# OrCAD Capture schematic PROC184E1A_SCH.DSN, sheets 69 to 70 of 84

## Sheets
69 28. SoM PMIC A: size C; title: PMIC A; note: PROC184_SCH
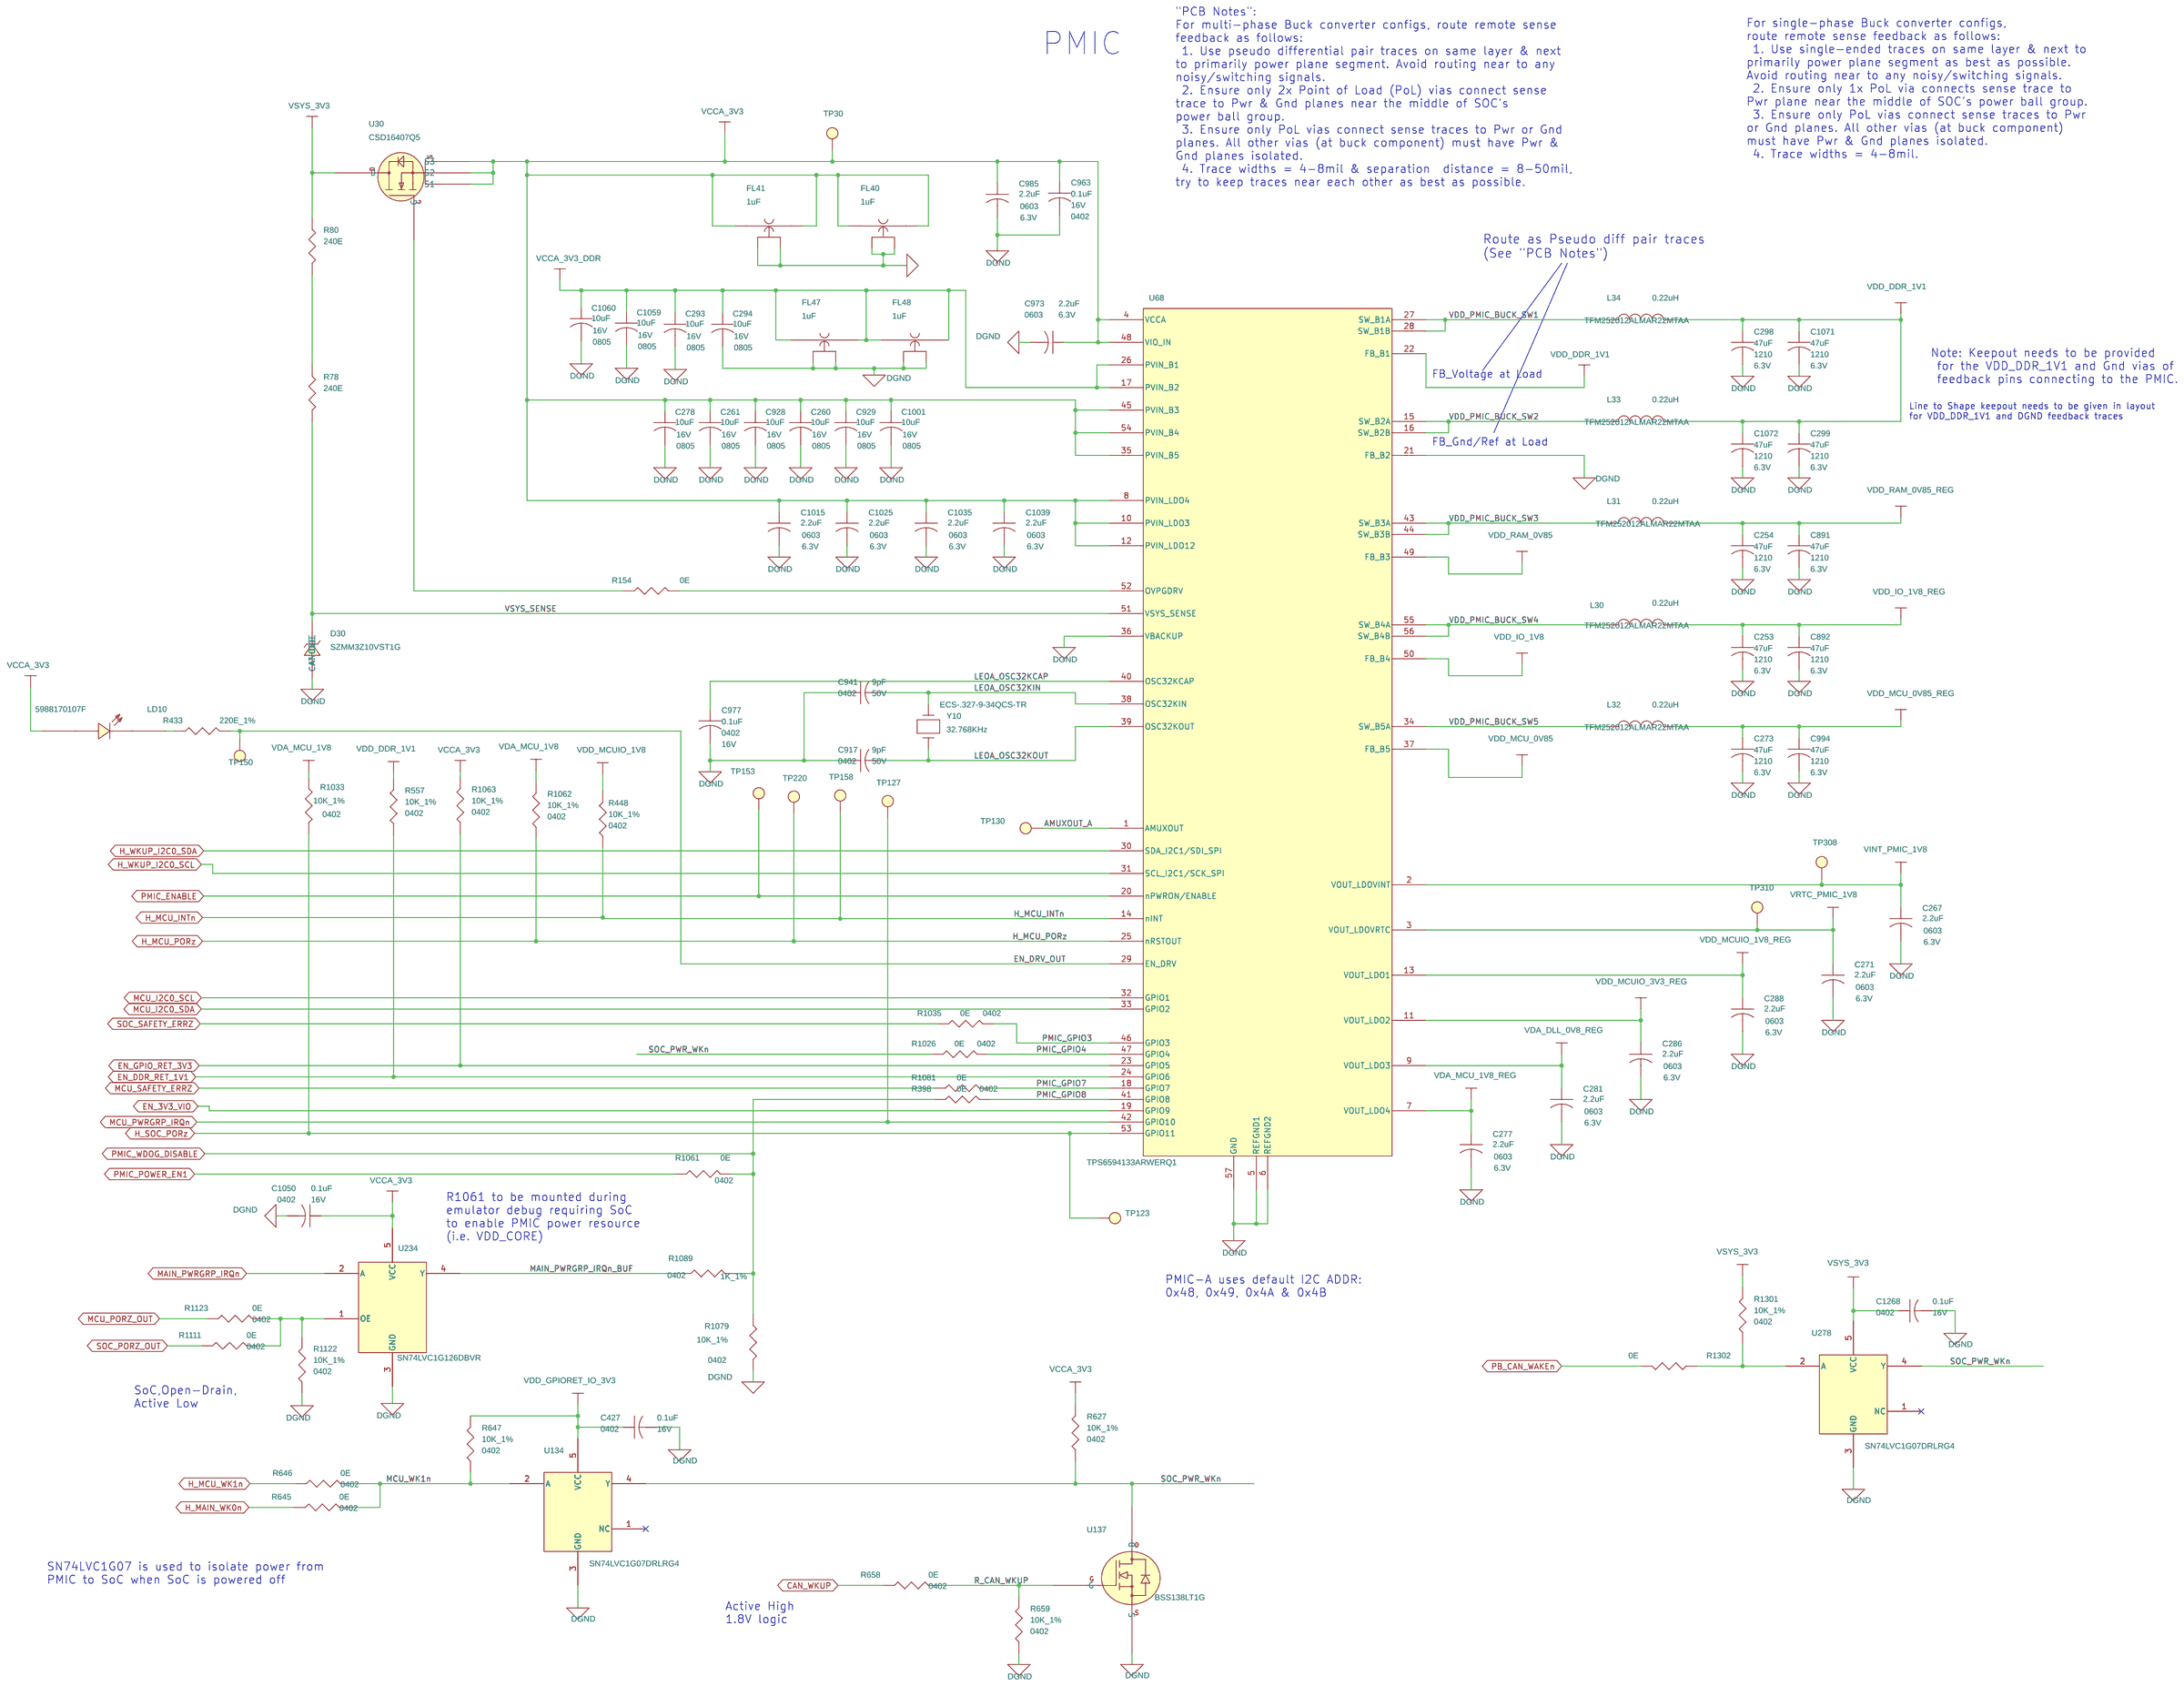
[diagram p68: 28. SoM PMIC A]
70 29. SOC CPU HCPS-A: size C; title: HCPS A; note: PROC184_SCH
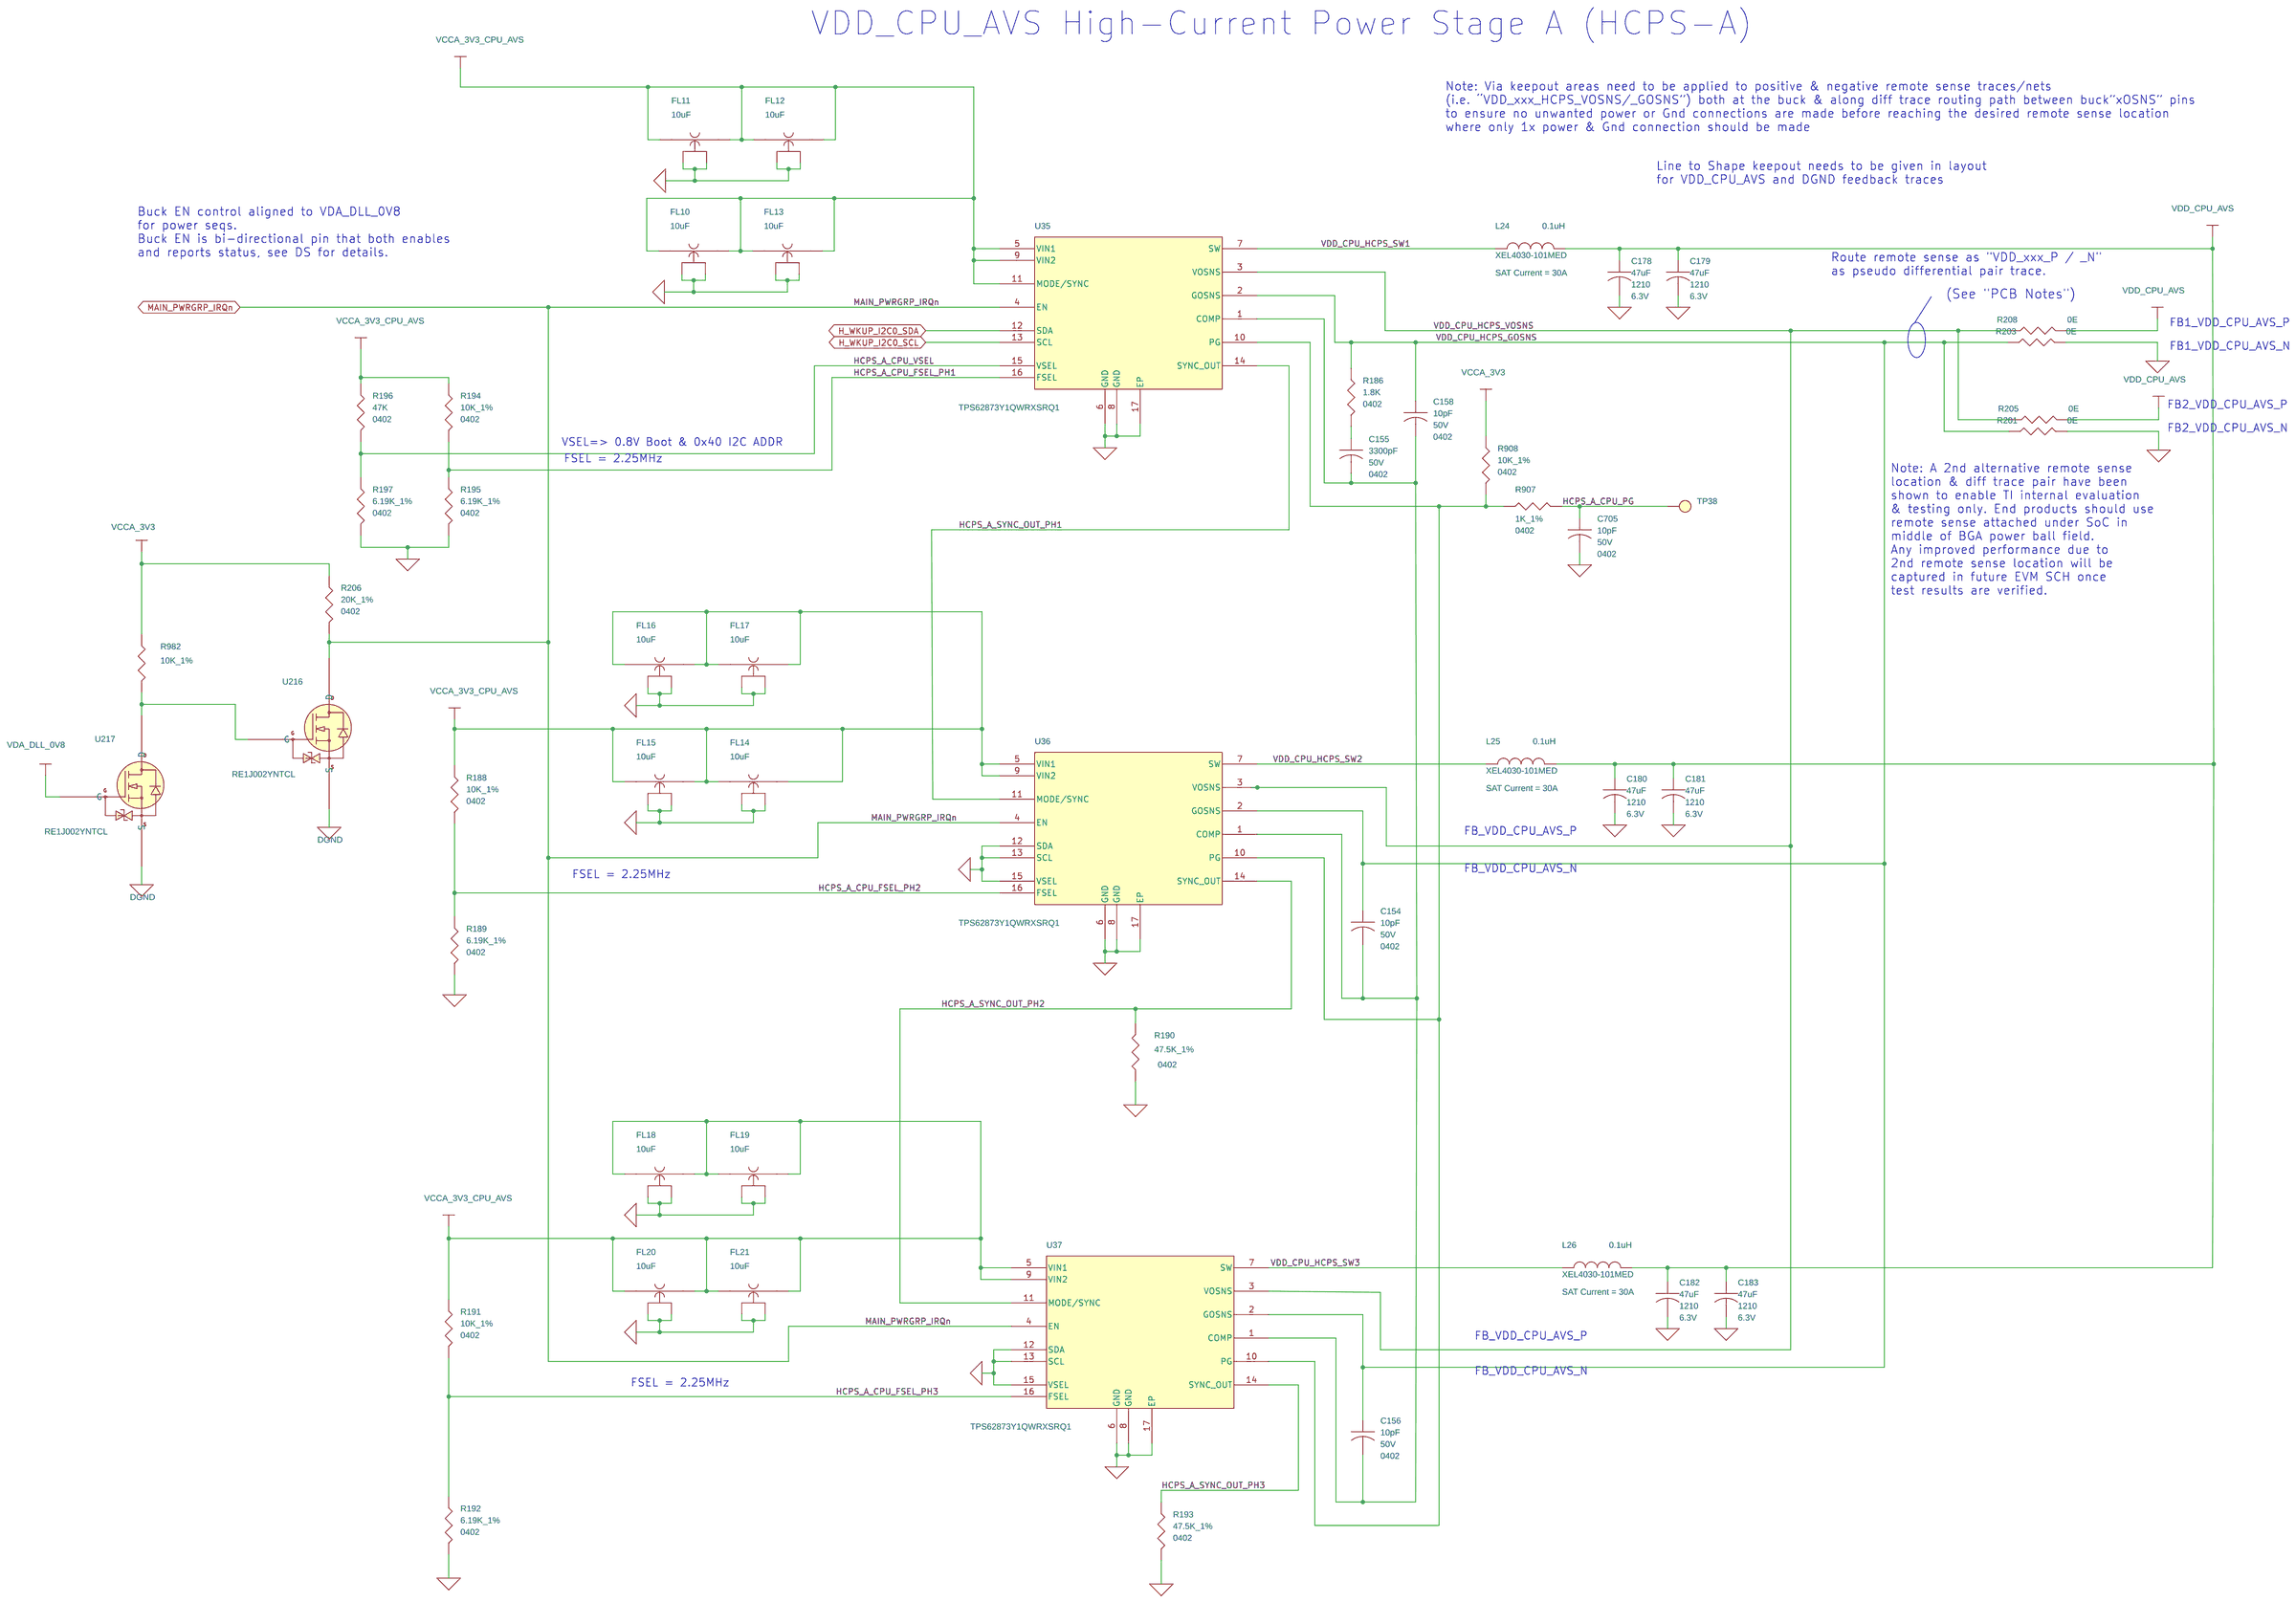
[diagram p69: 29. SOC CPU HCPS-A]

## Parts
sheet 28. SoM PMIC A
C253  47uF  [CAP1210_2-75]
C254  47uF  [CAP1210_2-75]
C260  10uF  [CAP0805_1-5]
C261  10uF  [CAP0805_1-5]
C267  2.2uF  [CAP0603_1]
C271  2.2uF  [CAP0603_1]
C273  47uF  [CAP1210_2-75]
C277  2.2uF  [CAP0603_1]
C278  10uF  [CAP0805_1-5]
C281  2.2uF  [CAP0603_1]
C286  2.2uF  [CAP0603_1]
C288  2.2uF  [CAP0603_1]
C293  10uF  [CAP0805_1-5]
C294  10uF  [CAP0805_1-5]
C298  47uF  [CAP1210_2-75]
C299  47uF  [CAP1210_2-75]
C427  0.1uF  [CAP0402_0-75]
C891  47uF  [CAP1210_2-75]
C892  47uF  [CAP1210_2-75]
C917  9pF  [CAP0402_0-75]
C928  10uF  [CAP0805_1-5]
C929  10uF  [CAP0805_1-5]
C941  9pF  [CAP0402_0-75]
C963  0.1uF  [CAP0402_0-75]
C973  2.2uF  [CAP0603_1]
C977  0.1uF  [CAP0402_0-75]
C985  2.2uF  [CAP0603_1]
C994  47uF  [CAP1210_2-75]
C1001  10uF  [CAP0805_1-5]
C1015  2.2uF  [CAP0603_1]
C1025  2.2uF  [CAP0603_1]
C1035  2.2uF  [CAP0603_1]
C1039  2.2uF  [CAP0603_1]
C1050  0.1uF  [CAP0402_0-75]
C1059  10uF  [CAP0805_1-5]
C1060  10uF  [CAP0805_1-5]
C1071  47uF  [CAP1210_2-75]
C1072  47uF  [CAP1210_2-75]
C1268  0.1uF  [CAP0402_0-75]
D30  SZMM3Z10VST1G  [DIO_SOD323_1-1]
FL40  1uF  [EMIFIL_NFM15CC_0402_0-5_TI]
FL41  1uF  [EMIFIL_NFM15CC_0402_0-5_TI]
FL47  1uF  [EMIFIL_NFM15CC_0402_0-5_TI]
FL48  1uF  [EMIFIL_NFM15CC_0402_0-5_TI]
L30  0.22uH  [IND1008_1-2]
L31  0.22uH  [IND1008_1-2]
L32  0.22uH  [IND1008_1-2]
L33  0.22uH  [IND1008_1-2]
L34  0.22uH  [IND1008_1-2]
LD10  5988170107F  [LED_0805_0-7]
R78  240E  [RES0402_0-5]
R80  240E  [RES0402_0-5]
R154  0E  [RES0402_0-5]
R398  0E  [RES0402_0-5]
R433  220E_1%  [RES0402_0-5]
R448  10K_1%  [RES0402_0-5]
R557  10K_1%  [RES0402_0-5]
R627  10K_1%  [RES0402_0-5]
R645  0E  [RES0402_0-5]
R646  0E  [RES0402_0-5]
R647  10K_1%  [RES0402_0-5]
R658  0E  [RES0402_0-5]
R659  10K_1%  [RES0402_0-5]
R1026  0E  [RES0402_0-5]
R1033  10K_1%  [RES0402_0-5]
R1035  0E  [RES0402_0-5]
R1061  0E  [RES0402_0-5]
R1062  10K_1%  [RES0402_0-5]
R1063  10K_1%  [RES0402_0-5]
R1079  10K_1%  [RES0402_0-5]
R1081  0E  [RES0402_0-5]
R1089  1K_1%  [RES0402_0-5]
R1111  0E  [RES0402_0-5]
R1122  10K_1%  [RES0402_0-5]
R1123  0E  [RES0402_0-5]
R1301  10K_1%  [RES0402_0-5]
R1302  0E  [RES0402_0-5]
TP30  TP30_SMD  [TP30_SMD]
TP123  TP30_SMD  [TP30_SMD]
TP127  TP30_SMD  [TP30_SMD]
TP130  TP30_SMD  [TP30_SMD]
TP150  TP30_SMD  [TP30_SMD]
TP153  TP30_SMD  [TP30_SMD]
TP158  TP30_SMD  [TP30_SMD]
TP220  TP30_SMD  [TP30_SMD]
TP308  TP30_SMD  [TP30_SMD]
TP310  TP30_SMD  [TP30_SMD]
U30  CSD16407Q5  [VSON8_CSD16407Q5_240X200_1-1]
U68  TPS6594133ARWERQ1  [VQFN56_19-68_320X320_0-9_EP6]
U134  SN74LVC1G07DRLRG4  [SOT553-5_0-6]
U137  BSS138LT1G  [SOT23-123_1-2]
U234  SN74LVC1G126DBVR  [SOT23-5_1-5]
U278  SN74LVC1G07DRLRG4  [SOT553-5_0-6]
Y10  32.768KHz  [XTAL_ECS-32_130X60_SMD_0-9]
sheet 29. SOC CPU HCPS-A
C154  10pF  [CAP0402_0-75]
C155  3300pF  [CAP0402_0-75]
C156  10pF  [CAP0402_0-75]
C158  10pF  [CAP0402_0-75]
C178  47uF  [CAP1210_2-75]
C179  47uF  [CAP1210_2-75]
C180  47uF  [CAP1210_2-75]
C181  47uF  [CAP1210_2-75]
C182  47uF  [CAP1210_2-75]
C183  47uF  [CAP1210_2-75]
C705  10pF  [CAP0402_0-75]
FL10  10uF  [EMIFIL_NFM18C_0603_0-7_TI]
FL11  10uF  [EMIFIL_NFM18C_0603_0-7_TI]
FL12  10uF  [EMIFIL_NFM18C_0603_0-7_TI]
FL13  10uF  [EMIFIL_NFM18C_0603_0-7_TI]
FL14  10uF  [EMIFIL_NFM18C_0603_0-7_TI]
FL15  10uF  [EMIFIL_NFM18C_0603_0-7_TI]
FL16  10uF  [EMIFIL_NFM18C_0603_0-7_TI]
FL17  10uF  [EMIFIL_NFM18C_0603_0-7_TI]
FL18  10uF  [EMIFIL_NFM18C_0603_0-7_TI]
FL19  10uF  [EMIFIL_NFM18C_0603_0-7_TI]
FL20  10uF  [EMIFIL_NFM18C_0603_0-7_TI]
FL21  10uF  [EMIFIL_NFM18C_0603_0-7_TI]
L24  0.1uH  [IND_XEL4030_170X170_SMD_3-2]
L25  0.1uH  [IND_XEL4030_170X170_SMD_3-2]
L26  0.1uH  [IND_XEL4030_170X170_SMD_3-2]
R186  1.8K  [RES0402_0-5]
R188  10K_1%  [RES0402_0-5]
R189  6.19K_1%  [RES0402_0-5]
R190  47.5K_1%  [RES0402_0-5]
R191  10K_1%  [RES0402_0-5]
R192  6.19K_1%  [RES0402_0-5]
R193  47.5K_1%  [RES0402_0-5]
R194  10K_1%  [RES0402_0-5]
R195  6.19K_1%  [RES0402_0-5]
R196  47K  [RES0402_0-5]
R197  6.19K_1%  [RES0402_0-5]
R201  0E  [RES0402_0-5]
R203  0E  [RES0402_0-5]
R205  0E  [RES0402_0-5]
R206  20K_1%  [RES0402_0-5]
R208  0E  [RES0402_0-5]
R907  1K_1%  [RES0402_0-5]
R908  10K_1%  [RES0402_0-5]
R982  10K_1%  [RES0402_0-5]
TP38  TP30_SMD  [TP30_SMD]
U35  TPS62873Y1QWRXSRQ1  [VQFN16_TPS62872-Q1_100X140_1-1]
U36  TPS62873Y1QWRXSRQ1  [VQFN16_TPS62872-Q1_100X140_1-1]
U37  TPS62873Y1QWRXSRQ1  [VQFN16_TPS62872-Q1_100X140_1-1]
U216  RE1J002YNTCL  [SOT416F-6_0-9]
U217  RE1J002YNTCL  [SOT416F-6_0-9]

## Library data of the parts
C178-C183 C253 C254 C273 C298 C299 C891 C892 C994 C1071 C1072 = CAP: CAP CERAMIC 47uF 6.3V 10% X7R AUTO 1210; Automotive Alternate_mfr_name: TDK; Automotive Alternate_mfr_part_number: CGA6P1X7S1A476M; Chkd/date: MANIRAJA/280918; Crtd /date: ALVY/280918; Custom_Duty: 15%; Customs_HS_Code: 85322990; Direct Alternate_mfr_name: TDK; Direct Alternate_mfr_part_number: CGA6P1X7S1A476M; Distributor_name: DIGIKEY; Distributor_part_number: 490-4844-1-ND; Footprint Path: Y:\MIS_DATABASE\Library\ALTIUM_TOOL\PCB_FOOTPRINTS\Altium_Footprint_Lib.PcbLib; Height: 2.70MM; Library Path: Y:\MIS_DATABASE\Library\ALTIUM_TOOL\SCHEMATICS_PARTS\MS_DISCRETE_Library.schlib; Manufacturer: MURATA; Mfr_name: MURATA; Mfr_part_number: GCM32ER70J476KE19L; Mistral Part No: 120018090056-R; Package: 1210; Part_type: CAPACITORS\CERAMIC; Project: TI_J7_SVB-DUT; RoHS: RoHS; Temperature: -55°C+125°C; Tolerance: 10%; Voltage: 6.3V; Wattage: NA; Weight: 110mg; Datasheet: Y:\MIS_DATABASE\DATASHEETS\CAPACITORS\MURATA-GCM-SER.PDF
C260 C261 C278 C293 C294 C928 C929 C1001 C1059 C1060 = CAP: CAP CERAMIC 10uF 16V 10% X5R 0805; Automotive Alternate_mfr_name: MURATA; Automotive Alternate_mfr_part_number: GCM21BR71A106KE22L; Chkd/date: SHREESHAIL/220506; Crtd /date: MAZHAR/150506; Custom_Duty: 15%; Customs_HS_Code: 85322990; Direct Alternate_mfr_name: SAMSUNG; Direct Alternate_mfr_part_number: CL21B106KPQNNNE; Distributor_name: DIGIKEY; Distributor_part_number: 490-3886-1-ND; Footprint Path: Y:\MIS_DATABASE\Library\ALTIUM_TOOL\PCB_FOOTPRINTS\Altium_Footprint_Lib.PcbLib; Height: 1.35MM; Library Path: Y:\MIS_DATABASE\Library\ALTIUM_TOOL\SCHEMATICS_PARTS\MS_DISCRETE_Library.schlib; Manufacturer: MURATA; Mfr_name: MURATA; Mfr_part_number: GRM21BR61C106KE15L; Mistral Part No: 120009030205-R; Package: 0805; Part_type: CAPACITORS\CERAMIC; Project: VOCERA; RoHS: RoHS; Temperature: -55°C+85°C; Tolerance: 10%; Voltage: 16V; Wattage: NA; Weight: 9.5mg; Datasheet: Y:\MIS_DATABASE\DATASHEETS\CAPACITORS\MURATA-GXX-SER_NOV17.PDF
C267 C271 C277 C281 C286 C288 C973 C985 C1015 C1025 C1035 C1039 = CAP: CAP CERAMIC 2.2uF 6.3V 10% X7R AUTO 0603; Automotive Alternate_mfr_name: TDK; Automotive Alternate_mfr_part_number: CGA3E1X7R0J225K080AC; Chkd/date: MANIRAJA/050419; Crtd /date: ALVY/050419; Custom_Duty: 15%; Customs_HS_Code: 85322990; Direct Alternate_mfr_name: TDK; Direct Alternate_mfr_part_number: CGA3E1X7R0J225K080AC; Distributor_name: DIGIKEY; Distributor_part_number: 490-5316-1-ND; Footprint Path: Y:\MIS_DATABASE\Library\ALTIUM_TOOL\PCB_FOOTPRINTS\Altium_Footprint_Lib.PcbLib; Height: 0.90MM; Library Path: Y:\MIS_DATABASE\Library\ALTIUM_TOOL\SCHEMATICS_PARTS\MS_DISCRETE_Library.schlib; Manufacturer: MURATA; Mfr_name: MURATA; Mfr_part_number: GCM188R70J225KE22D; Mistral Part No: 120019040009-R; Package: 0603; Part_type: CAPACITORS\CERAMIC; Project: J7ES_SOM_DUAL-LEO_PMIC; RoHS: RoHS; Temperature: -55°C+125°C; Tolerance: 10%; Voltage: 6.3V; Wattage: NA; Weight: 6.3mg; Datasheet: Y:\MIS_DATABASE\DATASHEETS\CAPACITORS\GCM188R70J225KE22.PDF
C427 C963 C977 C1050 C1268 = CAP: CAP CERAMIC 0.1uF 16V 10% X7R AUTO 0402; Automotive Alternate_mfr_name: TDK; Automotive Alternate_mfr_part_number: CGA2B1X7R1C104K050BC; Chkd/date: NAVEED/021014; Crtd /date: VASANTHA/300514; Custom_Duty: 15%; Customs_HS_Code: 85322990; Direct Alternate_mfr_name: MURATA; Direct Alternate_mfr_part_number: GCM155R71C104JA55D; Distributor_name: DIGIKEY; Distributor_part_number: 490-4759-1-ND; Footprint Path: Y:\MIS_DATABASE\Library\ALTIUM_TOOL\PCB_FOOTPRINTS\Altium_Footprint_Lib.PcbLib; Height: 0.55MM; Library Path: Y:\MIS_DATABASE\Library\ALTIUM_TOOL\SCHEMATICS_PARTS\MS_DISCRETE_Library.schlib; Manufacturer: MURATA; Mfr_name: MURATA; Mfr_part_number: GCM155R71C104KA55D; Mistral Part No: 120016070006-R; Package: 0402; Part_type: CAPACITORS\CERAMIC; Project: DCMIST_FPGA_CARD; RoHS: RoHS; Temperature: -55°C+125°C; Tolerance: 10%; Voltage: 16V; Wattage: NA; Weight: 6mg; Datasheet: Y:\MIS_DATABASE\DATASHEETS\CAPACITORS\MURATA-GCM-SER.PDF
C917 C941 = CAP: CAP CERAMIC 9pF 50V 0.5pF% C0G(NP0) AUTO 0402; Automotive Alternate_mfr_name: TDK; Automotive Alternate_mfr_part_number: CGA2B2C0G1H090D050BA; Chkd/date: VASANTHA/090419; Crtd /date: ALVY/090419; Custom_Duty: 15%; Customs_HS_Code: 85322990; Direct Alternate_mfr_name: TDK; Direct Alternate_mfr_part_number: CGA2B2C0G1H090D050BA; Distributor_name: DIGIKEY; Distributor_part_number: 445-12155-1-ND; Footprint Path: Y:\MIS_DATABASE\Library\ALTIUM_TOOL\PCB_FOOTPRINTS\Altium_Footprint_Lib.PcbLib; Height: 0.55MM; Library Path: Y:\MIS_DATABASE\Library\ALTIUM_TOOL\SCHEMATICS_PARTS\MS_DISCRETE_Library.schlib; Manufacturer: TDK CORPORATION; Mfr_name: TDK CORPORATION; Mfr_part_number: CGA2B2NP01H090D050BA; Mistral Part No: 120019040066-R; Package: 0402; Part_type: CAPACITORS\CERAMIC; Project: J7ES_SOM_DUAL-LEO_PMIC; RoHS: RoHS; Temperature: -55°C+150°C; Tolerance: 0.5pF%; Voltage: 50V; Wattage: NA; Weight: 0.65mg; Datasheet: Y:\MIS_DATABASE\DATASHEETS\CAPACITORS\CGA2B2NP01H090D050BA.PDF
D30 = DIODE_ZENER: DIODE ZENER 10V 300mW SOD323; Chkd/date: MANIRAJA/170419; Crtd /date: MANIRAJA/170419; Custom_Duty: 15%; Customs_HS_Code: 85412900; Distributor_name: DIGIKEY; Distributor_part_number: SZMM3Z10VST1GOSCT-ND; Footprint Path: Y:\MIS_DATABASE\Library\ALTIUM_TOOL\PCB_FOOTPRINTS\Altium_Footprint_Lib.PcbLib; Height: 1.10MM; Library Path: Y:\MIS_DATABASE\Library\ALTIUM_TOOL\SCHEMATICS_PARTS\MS_DISCRETE_Library.schlib; Manufacturer: ON SEMICONDUCTOR; Mfr_name: ON SEMICONDUCTOR; Mistral Part No: 130019040011-R; Package: SOD323; Part_type: DIODE\ZENER; Project: J7ES_SOM_DUAL-LEO_PMIC; RoHS: RoHS; Temperature: -65°C+150°C; Tolerance: NA; Voltage: 10V; Wattage: NA; Weight: NA; Datasheet: Y:\MIS_DATABASE\DATASHEETS\DISCRETES\DIODES\SZMM3ZXXXST1G.PDF
FL40 FL41 FL47 FL48 = CAP_NFM_TI: PASSIVE FILTER EMI 1uF 4V AUTO 0402; Chkd/date: MANIRAJA/251018; Crtd /date: ALVY/251018; Custom_Duty: 15%; Customs_HS_Code: 85412900; Distributor_name: NA; Distributor_part_number: NA; Footprint Path: Y:\MIS_DATABASE\Library\ALTIUM_TOOL\PCB_FOOTPRINTS\Altium_Footprint_Lib.PcbLib; Height: 0.50MM; Library Path: Y:\MIS_DATABASE\Library\ALTIUM_TOOL\SCHEMATICS_PARTS\MS_FILTER_Library.schlib; Mfr_name: MURATA; Mfr_part_number: NFM15HC105D0G_TI; Mistral Part No: 130018100050; Package: 0402; Part_type: FILTER; Project: TI_J7ES_EVM_SOM; RoHS: NA; Temperature: NA; Tolerance: NA; Voltage: 4V; Wattage: NA; Weight: NA; Datasheet: Y:\MIS_DATABASE\DATASHEETS\DISCRETES\INDUCTORS\NFM15CC223C1A3.PDF
L30-L34 = INDUCTOR: IND POWER 0.22uH 6.7A 20% AUTO 1008; Chkd/date: MANIRAJA/010620; Crtd /date: ALVY/290520; Custom_Duty: 24%; Customs_HS_Code: 85437099; Distributor_name: DIGIKEY; Distributor_part_number: 445-181487-1-ND; Footprint Path: Y:\MIS_DATABASE\Library\ALTIUM_TOOL\PCB_FOOTPRINTS\Altium_Footprint_Lib.PcbLib; Height: 1.20MM; Library Path: Y:\MIS_DATABASE\Library\ALTIUM_TOOL\SCHEMATICS_PARTS\MS_DISCRETE_Library.schlib; Manufacturer: TDK CORPORATION; Mfr_name: TDK CORPORATION; Mfr_part_number: TFM252012ALMAR22MTAA; Mistral Part No: 130020060001-R; Package: 1008; Project: J7VCL_SOM_LEO_HERA PMIC BRD; RoHS: RoHS; Temperature: -55°C+150°C; Tolerance: 20%; Voltage: NA; Wattage: NA; Weight: 35mg; Datasheet: Y:\MIS_DATABASE\DATASHEETS\DISCRETES\INDUCTORS\TFM252012ALMA-SER.PDF
LD10 = LED_598-8170-107F: LED ALINGAP GREEN CLEAR 0805; Chkd/date: MANIRAJA/230817; Crtd /date: SARANYA/070514; Custom_Duty: 24%; Customs_HS_Code: 85437099; Distributor_name: DIGIKEY; Distributor_part_number: 350-2044-1-ND; Footprint Path: Y:\MIS_DATABASE\Library\ALTIUM_TOOL\PCB_FOOTPRINTS\Altium_Footprint_Lib.PcbLib; Height: 0.70MM; Manufacturer: DIALIGHT; Mfr_name: DIALIGHT; Mistral Part No: 130014050065-R; Package: 0805; Part_type: OPTO\LED; Project: AEGIS GP BETA2; RoHS: RoHS; Temperature: -30°C+85°C; Tolerance: NA; Voltage: NA; Wattage: NA; Weight: NA; Datasheet: Y:\MIS_DATABASE\DATASHEETS\DISCRETES\LEDS\598-SER.PDF
R78 R80 = RESISTOR: RES 240E 1/16W 5% 0402; Chkd/date: VASANTHA/060117; Crtd /date: GEETHA/070606; Custom_Duty: 15%; Customs_HS_Code: 85332119; Distributor_name: DIGIKEY; Distributor_part_number: 311-240JRCT-ND; Footprint Path: Y:\MIS_DATABASE\Library\ALTIUM_TOOL\PCB_FOOTPRINTS\Altium_Footprint_Lib.PcbLib; Height: 0.40MM; Library Path: Y:\MIS_DATABASE\Library\ALTIUM_TOOL\SCHEMATICS_PARTS\MS_DISCRETE_Library.schlib; Manufacturer: YAGEO AMERICA; Mfr_name: YAGEO AMERICA; Mfr_part_number: RC0402JR-07240RL; Mistral Part No: 110009030544-R; Package: 0402; Part_type: RESISTORS\FIXED; Project: VOCERA; RoHS: RoHS; Temperature: -55°C+155°C; Tolerance: 5%; Voltage: NA; Wattage: 1/16W; Weight: 0.65mg; Datasheet: Y:\MIS_DATABASE\DATASHEETS\RESISTORS\RCXXXXL-SER_MAR18.PDF
R154 R201 R203 R205 R208 R398 R645 R646 R658 R1026 R1035 R1061 R1081 R1111 R1123 R1302 = RESISTOR: RES 0E 1/10W JUMPER 0402; Chkd/date: VASANTHA/061216; Crtd /date: NAVEED/201014; Custom_Duty: 15%; Customs_HS_Code: 85332119; Distributor_name: DIGIKEY; Distributor_part_number: P0.0JCT-ND; Footprint Path: Y:\MIS_DATABASE\Library\ALTIUM_TOOL\PCB_FOOTPRINTS\Altium_Footprint_Lib.PcbLib; Height: 0.40MM; IBISSP_MODLES: VALUE REPEATING 2 TIME; Library Path: Y:\MIS_DATABASE\Library\ALTIUM_TOOL\SCHEMATICS_PARTS\MS_DISCRETE_Library.schlib; Manufacturer: PANASONIC-ECG; Mfr_name: PANASONIC-ECG; Mfr_part_number: ERJ-2GE0R00X; Mistral Part No: 110018030052-R; Package: 0402; Part_type: RESISTORS\FIXED; Project: AEGIS POM; RoHS: RoHS; Temperature: -55°C+155°C; Tolerance: NA; Voltage: NA; Wattage: 1/10W; Weight: 0.8mg; Datasheet: Y:\MIS_DATABASE\DATASHEETS\RESISTORS\PAN-ERJSER_NOV17.PDF
R433 = RESISTOR: RES 220E 1/16W 1% 0402; Chkd/date: MANIRAJA/130917; Crtd /date: MANIRAJA/130917; Custom_Duty: 15%; Customs_HS_Code: 85332119; Distributor_name: DIGIKEY; Distributor_part_number: 311-220LRCT-ND; Footprint Path: Y:\MIS_DATABASE\Library\ALTIUM_TOOL\PCB_FOOTPRINTS\Altium_Footprint_Lib.PcbLib; Height: 0.40MM; Library Path: Y:\MIS_DATABASE\Library\ALTIUM_TOOL\SCHEMATICS_PARTS\MS_DISCRETE_Library.schlib; Manufacturer: YAGEO AMERICA; Mfr_name: YAGEO AMERICA; Mfr_part_number: RC0402FR-07220RL; Mistral Part No: 110019040169-R; Package: 0402; Part_type: RESISTORS\FIXED; Project: TI_SVB_MAXWELL_DUT; RoHS: RoHS; Temperature: -55°C+155°C; Tolerance: 1%; Voltage: NA; Wattage: 1/16W; Weight: 0.65mg; Datasheet: Y:\MIS_DATABASE\DATASHEETS\RESISTORS\RCXXXXL-SER_MAR18.PDF
R188 R191 R194 R448 R557 R627 R647 R659 R908 R1033 R1062 R1063 R1079 R1122 R1301 = RESISTOR: RES 10K 1/16W 1% 0402; Chkd/date: VASANTHA/201216; Crtd /date: GEETHA/290506; Custom_Duty: 15%; Customs_HS_Code: 85332119; Distributor_name: DIGIKEY; Distributor_part_number: 311-10.0KLRTR-ND; Footprint Path: Y:\MIS_DATABASE\Library\ALTIUM_TOOL\PCB_FOOTPRINTS\Altium_Footprint_Lib.PcbLib; Height: 0.40MM; Library Path: Y:\MIS_DATABASE\Library\ALTIUM_TOOL\SCHEMATICS_PARTS\MS_DISCRETE_Library.schlib; Manufacturer: YAGEO AMERICA; Mfr_name: YAGEO AMERICA; Mfr_part_number: RC0402FR-0710KL; Mistral Part No: 110015090015-R; Package: 0402; Part_type: RESISTORS\FIXED; Project: VOCERA; RoHS: RoHS; Temperature: -55°C+155°C; Tolerance: 1%; Voltage: NA; Wattage: 1/16W; Weight: 0.65mg; Datasheet: Y:\MIS_DATABASE\DATASHEETS\RESISTORS\RCXXXXL-SER_MAR18.PDF
R907 R1089 = RESISTOR: RES 1K 1/10W 1% 0402; Chkd/date: VASANTHA/281216; Crtd /date: MAZHAR/150506; Custom_Duty: 15%; Customs_HS_Code: 85332119; Distributor_name: DIGIKEY; Distributor_part_number: P1.00KLCT-ND; Footprint Path: Y:\MIS_DATABASE\Library\ALTIUM_TOOL\PCB_FOOTPRINTS\Altium_Footprint_Lib.PcbLib; Height: 0.40MM; Library Path: Y:\MIS_DATABASE\Library\ALTIUM_TOOL\SCHEMATICS_PARTS\MS_DISCRETE_Library.schlib; Manufacturer: PANASONIC-ECG; Mfr_name: PANASONIC-ECG; Mfr_part_number: ERJ-2RKF1001X; Mistral Part No: 110009030411-R; Package: 0402; Part_type: RESISTORS\FIXED; Project: VOCERA; RoHS: RoHS; Temperature: -55°C+155°C; Tolerance: 1%; Voltage: NA; Wattage: 1/10W; Weight: 0.8mg; Datasheet: Y:\MIS_DATABASE\DATASHEETS\RESISTORS\PAN-ERJSER_NOV17.PDF
TP30 TP38 TP123 TP127 TP130 TP150 TP153 TP158 TP220 TP308 TP310 = TESTPOINT: TESTPOINT CIR 30 SMD; Chkd/date: SHREESHAIL/171006; Crtd /date: MAZHAR/171006; Custom_Duty: NA; Customs_HS_Code: NA; Distributor_name: NA; Distributor_part_number: NA; Footprint Path: Y:\MIS_DATABASE\Library\ALTIUM_TOOL\PCB_FOOTPRINTS\Altium_Footprint_Lib.PcbLib; Height: NA; Library Path: Y:\MIS_DATABASE\Library\ALTIUM_TOOL\SCHEMATICS_PARTS\MS_DISCRETE_Library.schlib; MECHANICAL 3D STEP FILE: NA; Manufacturer: LOCAL; Mfr_name: LOCAL; Mistral Part No: 130009030930; Package: SMD; Project: BT MODULE_CSRBC04; RoHS: NA; Temperature: NA; Tolerance: NA; Voltage: NA; Wattage: NA; Weight: NA; Datasheet: NA
U30 = MOSFET_CSD17301Q5A: IC 25V N-CHANNEL NEXFET POWER MOSFET VSON-CLIP8; Chkd/date: ALVY/090322; Crtd /date: ALVY/090322; Custom_Duty: 15%; Customs_HS_Code: 85423100; Distributor_name: DIGIKEY; Distributor_part_number: 296-24252-1-ND; Footprint Path: Y:\MIS_DATABASE\Library\ALTIUM_TOOL\PCB_FOOTPRINTS\Altium_Footprint_Lib.PcbLib; Height: 1.05MM; Library Path: Y:\MIS_DATABASE\Library\ALTIUM_TOOL\SCHEMATICS_PARTS\MS_MOSFET_Library.schlib; Mfr_name: TEXAS INSTRUMENTS; Mistral Part No: 142022030005-R; Package: VSON-CLIP8; Part_type: ICS\POWER\MOSFET; Project: TI_J7AHP_EVM_BRD; RoHS: RoHS; Temperature: -55°C+150°C; Tolerance: NA; Voltage: 25V; Wattage: NA; Weight: 117.4mg; Datasheet: Y:\MIS_DATABASE\DATASHEETS\ICS\POWER\CSD16407Q5.PDF
U68 = TPS65941-Q1_VQFN56: IC POWER MANAGEMENT WITH 4-PHASE 14A BUCK VQFN56; Chkd/date: ALVY/280322; Crtd /date: ALVY/280322; Custom_Duty: 15%; Customs_HS_Code: 85423100; Distributor_name: NA; Distributor_part_number: NA; Footprint Path: Y:\MIS_DATABASE\Library\ALTIUM_TOOL\PCB_FOOTPRINTS\Altium_Footprint_Lib.PcbLib; Height: 0.90MM; Library Path: Y:\MIS_DATABASE\Library\ALTIUM_TOOL\SCHEMATICS_PARTS\MS_MISCPOWER_Library.schlib; Manufacturer: TEXAS INSTRUMENTS; Mfr_name: TEXAS INSTRUMENTS; Mistral Part No: 142022030021-R; Package: VQFN56; Part_type: ICS\POWER\MANAGEMENT; Project: TI_J7AHP_EVM_BRD; Remarks: CREATED SAME AS PTPS65941120RWERQ1; RoHS: RoHS; Temperature: -40°C+125°C; Tolerance: NA; Voltage: NA; Wattage: NA; Weight: NA; Datasheet: Y:\MIS_DATABASE\DATASHEETS\ICS\POWER\TPS65941-Q1.PDF
U134 U278 = SN74LVC1G07DRLRG4_SOT553-5: IC SINGLE BUFFER/DRIVER WITH OPEN-DRAIN OUTPUT SOT553-5; Chkd/date: RAGESH/111110; Crtd /date: MAZHAR/170907; Custom_Duty: 15%; Customs_HS_Code: 85423100; Distributor_name: DIGIKEY; Distributor_part_number: SN74LVC1G07DRLRG4-ND; Footprint Path: Y:\MIS_DATABASE\Library\ALTIUM_TOOL\PCB_FOOTPRINTS\Altium_Footprint_Lib.PcbLib; Height: 0.60MM; Library Path: Y:\MIS_DATABASE\Library\ALTIUM_TOOL\SCHEMATICS_PARTS\MS_LINEDRIVERRECEIVER_Library.schlib; Manufacturer: TEXAS INSTRUMENTS; Mfr_name: TEXAS INSTRUMENTS; Mistral Part No: 141009030406-R; Package: SOT553-5; Part_type: ICS\INTERFACE\LINE DRIVER; Project: SMART VIEW_IP CAMERA; RoHS: RoHS; Temperature: -40°C+125°C; Tolerance: NA; Voltage: NA; Wattage: NA; Weight: 2.8mg; Datasheet: Y:\MIS_DATABASE\DATASHEETS\ICS\INTERFACE\SN74LVC1G07-SER.PDF
U137 = MOSFET_BSS138W: IC MOSFET N-CHANNEL 50V 200mA SOT23-3; Chkd/date: MANIRAJA/250219; Crtd /date: JEBRAN/060416; Custom_Duty: 15%; Customs_HS_Code: 85423100; Distributor_name: DIGIKEY; Distributor_part_number: BSS138LT1GOSCT-ND; Footprint Path: Y:\MIS_DATABASE\Library\ALTIUM_TOOL\PCB_FOOTPRINTS\Altium_Footprint_Lib.PcbLib; Height: 1.11MM; Library Path: Y:\MIS_DATABASE\Library\ALTIUM_TOOL\SCHEMATICS_PARTS\MS_MOSFET_Library.schlib; Manufacturer: ON SEMICONDUCTOR; Mfr_name: ON SEMICONDUCTOR; Mistral Part No: 142016040001-R; Package: SOT23-3; Part_type: ICS\POWER\MOSFET; Project: LRDE_ABCM; RoHS: RoHS; Temperature: -55°C+150°C; Tolerance: NA; Voltage: NA; Wattage: NA; Weight: 8mg; Datasheet: Y:\MIS_DATABASE\DATASHEETS\DISCRETES\TRANSISTORS_FETS\BSS138LT1G.PDF
U234 = SN74LVC1G126DBVR_SOT23-5: IC SINGLE BUS BUFFER GATE WITH 3-STATE O/P SOT23-5; Chkd/date: MANIRAJA/130519; Crtd /date: MAZHAR/301106; Custom_Duty: 15%; Customs_HS_Code: 85423100; Distributor_name: DIGIKEY; Distributor_part_number: 296-11605-1-ND; Footprint Path: Y:\MIS_DATABASE\Library\ALTIUM_TOOL\PCB_FOOTPRINTS\Altium_Footprint_Lib.PcbLib; Height: 1.45MM; Library Path: Y:\MIS_DATABASE\Library\ALTIUM_TOOL\SCHEMATICS_PARTS\MS_GATE_Library.schlib; Mfr_name: TEXAS INSTRUMENTS; Mistral Part No: 141009030232-R; Package: SOT23-5; Part_type: ICS\DIGITAL\GATES; Project: PMP LCD BOARD; RoHS: RoHS; Temperature: -40°C+125°C; Tolerance: NA; Voltage: NA; Wattage: NA; Weight: 6.3mg; Datasheet: Y:\MIS_DATABASE\DATASHEETS\ICS\DIGITAL\GATES\SN74LVC1G126XXX.PDF
Y10 = CRY: CRY 32.768KHz 9pF SMD; Chkd/date: VASANTHA/090419; Crtd /date: ALVY/090419; Custom_Duty: 24%; Customs_HS_Code: 85439000; Distributor_name: DIGIKEY; Distributor_part_number: XC2160CT-ND; Footprint Path: Y:\MIS_DATABASE\Library\ALTIUM_TOOL\PCB_FOOTPRINTS\Altium_Footprint_Lib.PcbLib; Height: 0.90MM; Library Path: Y:\MIS_DATABASE\Library\ALTIUM_TOOL\SCHEMATICS_PARTS\MS_DISCRETE_Library.schlib; Manufacturer: ECS INC; Mfr_name: ECS INC; Mfr_part_number: ECS-.327-9-34QCS-TR; Mistral Part No: 130019040003-R; Package: SMD; Part_type: CRYSTAL; Project: J7ES_SOM_DUAL-LEO_PMIC; RoHS: RoHS; Temperature: -40°C+125°C; Tolerance: NA; Voltage: NA; Wattage: NA; Weight: 16mg; Datasheet: Y:\MIS_DATABASE\DATASHEETS\MISC\CRY_OSC\ECS-34Q.PDF
C154 C156 C158 C705 = CAP: CAP CERAMIC 10pF 50V 1% C0G(NP0) 0402; Automotive Alternate_mfr_name: TDK; Automotive Alternate_mfr_part_number: CGA2B1X7R1C104K050BC; Chkd/date: VASANTHA/200614; Crtd /date: NAVEED/170614; Custom_Duty: 15%; Customs_HS_Code: 85322990; Direct Alternate_mfr_name: MURATA; Direct Alternate_mfr_part_number: GCM155R71C104JA55D; Distributor_name: DIGIKEY; Distributor_part_number: 478-5717-1-ND; Footprint Path: Y:\MIS_DATABASE\Library\ALTIUM_TOOL\PCB_FOOTPRINTS\Altium_Footprint_Lib.PcbLib; Height: 0.55MM; Library Path: Y:\MIS_DATABASE\Library\ALTIUM_TOOL\SCHEMATICS_PARTS\MS_DISCRETE_Library.schlib; Manufacturer: AVX CORPORATION; Mfr_name: AVX CORPORATION; Mfr_part_number: 04025U100FAT2A; Mistral Part No: 120014060010-R; Package: 0402; Part_type: CAPACITORS\CERAMIC; Project: AEGIS_POM; RoHS: RoHS; Temperature: -55°C+125°C; Tolerance: 1%; Voltage: 50V; Wattage: NA; Weight: 0.65mg; Datasheet: Y:\MIS_DATABASE\DATASHEETS\CAPACITORS\AVX_MLC.PDF
C155 = CAP: CAP CERAMIC 3300pF 50V 10% X7R 0402; Automotive Alternate_mfr_name: TDK; Automotive Alternate_mfr_part_number: CGA2B1X7R1C104K050BC; Chkd/date: MANIRAJA/180817; Crtd /date: MANIRAJA/180817; Custom_Duty: 15%; Customs_HS_Code: 85322990; Direct Alternate_mfr_name: MURATA; Direct Alternate_mfr_part_number: GCM155R71C104JA55D; Distributor_name: DIGIKEY; Distributor_part_number: 490-3248-1-ND; Footprint Path: Y:\MIS_DATABASE\Library\ALTIUM_TOOL\PCB_FOOTPRINTS\Altium_Footprint_Lib.PcbLib; Height: 0.55MM; Library Path: Y:\MIS_DATABASE\Library\ALTIUM_TOOL\SCHEMATICS_PARTS\MS_DISCRETE_Library.schlib; Manufacturer: MURATA; Mfr_name: MURATA; Mfr_part_number: GRM155R71H332KA01D; Mistral Part No: 120009030367-R; Package: 0402; Part_type: CAPACITORS\CERAMIC; Project: DM8147_PCI CARD; RoHS: RoHS; Temperature: -55°C+125°C; Tolerance: 10%; Voltage: 50V; Wattage: NA; Weight: 6mg; Datasheet: Y:\MIS_DATABASE\DATASHEETS\CAPACITORS\MURATA-GXX-SER_NOV17.PDF
FL10-FL21 = CAP_NFM_TI: PASSIVE FILTER EMI 10uF 4V AUTO 0603; Chkd/date: MANIRAJA/251018; Crtd /date: ALVY/251018; Custom_Duty: 15%; Customs_HS_Code: 85412900; Distributor_name: NA; Distributor_part_number: NA; Footprint Path: Y:\MIS_DATABASE\Library\ALTIUM_TOOL\PCB_FOOTPRINTS\Altium_Footprint_Lib.PcbLib; Height: 0.70MM; Library Path: Y:\MIS_DATABASE\Library\ALTIUM_TOOL\SCHEMATICS_PARTS\MS_FILTER_Library.schlib; Mfr_name: MURATA; Mfr_part_number: NFM18HC106D0G_TI; Mistral Part No: 130018100049; Package: 0603; Part_type: FILTER; Project: TI_J7ES_EVM_SOM; RoHS: NA; Temperature: NA; Tolerance: NA; Voltage: 4V; Wattage: NA; Weight: NA; Datasheet: Y:\MIS_DATABASE\DATASHEETS\DISCRETES\INDUCTORS\NFM18HC-SER.PDF
L24-L26 = INDUCTOR: IND POWER 0.1uH 25.8A 20% SMD; Chkd/date: MANIRAJA/170122; Crtd /date: TAMILARASU/170122; Custom_Duty: 24%; Customs_HS_Code: 85437099; Distributor_name: MOUSER; Distributor_part_number: 994-XEL4030-101MED; Footprint Path: Y:\MIS_DATABASE\Library\ALTIUM_TOOL\PCB_FOOTPRINTS\Altium_Footprint_Lib.PcbLib; Height: 3.20MM; Library Path: Y:\MIS_DATABASE\Library\ALTIUM_TOOL\SCHEMATICS_PARTS\MS_DISCRETE_Library.schlib; Manufacturer: COILCRAFT; Mfr_name: COILCRAFT; Mfr_part_number: XEL4030-101MED; Mistral Part No: 130022010018-R; Package: SMD; Part #: 105324-1470R; Project: J7AHP_PROTO_BRD; RoHS: RoHS; SAT Current: 30A; Temperature: -40°C+125°C; Tolerance: 20%; Voltage: NA; Wattage: NA; Weight: 280mg; Datasheet: Y:\MIS_DATABASE\DATASHEETS\DISCRETES\INDUCTORS\XEL4030_JUN20.PDF
R186 = RESISTOR: RES 1.8K 1/16W 5% AUTO 0402; Chkd/date: MAZHAR/170709; Crtd /date: MAZHAR/200907; Custom_Duty: 15%; Customs_HS_Code: 85332119; Distributor_name: DIGIKEY; Distributor_part_number: RHM1.8KJCT-ND; Footprint Path: Y:\MIS_DATABASE\Library\ALTIUM_TOOL\PCB_FOOTPRINTS\Altium_Footprint_Lib.PcbLib; Height: 0.40MM; Library Path: Y:\MIS_DATABASE\Library\ALTIUM_TOOL\SCHEMATICS_PARTS\MS_DISCRETE_Library.schlib; Manufacturer: ROHM; Mfr_name: ROHM; Mfr_part_number: MCR01MZPJ182; Mistral Part No: 110009030147-R; Package: 0402; Part_type: RESISTORS\FIXED; Project: MARP; RoHS: RoHS; Temperature: -55°C+155°C; Tolerance: 5%; Voltage: NA; Wattage: 1/16W; Weight: 0.57mg; Datasheet: Y:\MIS_DATABASE\DATASHEETS\RESISTORS\MCR10.PDF
R189 R192 R195 R197 = RESISTOR: RES 6.19K 1/16W 1% 0402; Chkd/date: MANIRAJA/190122; Crtd /date: TAMILARASU/190122; Custom_Duty: 15%; Customs_HS_Code: 85332119; Distributor_name: DIGIKEY; Distributor_part_number: 311-6.19KLRCT-ND; Footprint Path: Y:\MIS_DATABASE\Library\ALTIUM_TOOL\PCB_FOOTPRINTS\Altium_Footprint_Lib.PcbLib; Height: 0.40MM; Library Path: Y:\MIS_DATABASE\Library\ALTIUM_TOOL\SCHEMATICS_PARTS\MS_DISCRETE_Library.schlib; Manufacturer: YAGEO AMERICA; Mfr_name: YAGEO AMERICA; Mfr_part_number: RC0402FR-076K19L; Mistral Part No: 110022010013-R; Package: 0402; Part_type: RESISTORS\FIXED; Project: J7AHP_PROTO_BRD; RoHS: RoHS; Temperature: -55°C+155°C; Tolerance: 1%; Voltage: NA; Wattage: 1/16W; Weight: 0.65mg; Datasheet: Y:\MIS_DATABASE\DATASHEETS\RESISTORS\RCXXXXL-SER_MAR18.PDF
R190 R193 = RESISTOR: RES 47.5K 1/16W 1% 0402; Chkd/date: MANIRAJA/170320; Crtd /date: MANIRAJA/170320; Custom_Duty: 15%; Customs_HS_Code: 85332119; Distributor_name: DIGIKEY; Distributor_part_number: 541-47.5KLCT-ND; Footprint Path: Y:\MIS_DATABASE\Library\ALTIUM_TOOL\PCB_FOOTPRINTS\Altium_Footprint_Lib.PcbLib; Height: 0.40MM; Library Path: Y:\MIS_DATABASE\Library\ALTIUM_TOOL\SCHEMATICS_PARTS\MS_DISCRETE_Library.schlib; Manufacturer: VISHAY; Mfr_name: VISHAY; Mfr_part_number: CRCW040247K5FKED; Mistral Part No: 110017010006-R; Package: 0402; Part_type: RESISTORS\FIXED; Project: TPR12_SVB; RoHS: RoHS; Temperature: -55°C+155°C; Tolerance: 1%; Voltage: NA; Wattage: 1/16W; Weight: 0.65mg; Datasheet: Y:\MIS_DATABASE\DATASHEETS\RESISTORS\CRCW0603.PDF
R196 = RESISTOR: RES 47K 1/10W 5% 0402; Chkd/date: VASANTHA/281216; Crtd /date: MAZHAR/120505; Custom_Duty: 15%; Customs_HS_Code: 85332119; Distributor_name: DIGIKEY; Distributor_part_number: P47KJCT-ND; Footprint Path: Y:\MIS_DATABASE\Library\ALTIUM_TOOL\PCB_FOOTPRINTS\Altium_Footprint_Lib.PcbLib; Height: 0.40MM; Library Path: Y:\MIS_DATABASE\Library\ALTIUM_TOOL\SCHEMATICS_PARTS\MS_DISCRETE_Library.schlib; Manufacturer: PANASONIC-ECG; Mfr_name: PANASONIC-ECG; Mfr_part_number: ERJ-2GEJ473X; Mistral Part No: 110009030882-R; Package: 0402; Part_type: RESISTORS\FIXED; Project: CTP02_REVA_BASE; RoHS: RoHS; Temperature: -55°C+155°C; Tolerance: 5%; Voltage: NA; Wattage: 1/10W; Weight: 0.8mg; Datasheet: Y:\MIS_DATABASE\DATASHEETS\RESISTORS\PAN-ERJSER_NOV17.PDF
R206 = RESISTOR: RES 20K 1/16W 1% 0402; Chkd/date: MAZHAR/280108; Crtd /date: USMAN/280108; Custom_Duty: 15%; Customs_HS_Code: 85332119; Distributor_name: DIGIKEY; Distributor_part_number: 311-20.0KLRCT-ND; Footprint Path: Y:\MIS_DATABASE\Library\ALTIUM_TOOL\PCB_FOOTPRINTS\Altium_Footprint_Lib.PcbLib; Height: 0.40MM; Library Path: Y:\MIS_DATABASE\Library\ALTIUM_TOOL\SCHEMATICS_PARTS\MS_DISCRETE_Library.schlib; Mfr_name: YAGEO AMERICA; Mfr_part_number: RC0402FR-0720KL; Mistral Part No: 110009030486-R; Package: 0402; Part_type: RESISTORS\FIXED; Project: TELEMETRY ENCODER; RoHS: RoHS; Temperature: -55°C+155°C; Tolerance: 1%; Voltage: NA; Wattage: 1/16W; Weight: 0.65mg; Datasheet: Y:\MIS_DATABASE\DATASHEETS\RESISTORS\RCXXXXL-SER_MAR18.PDF
R982 = RESISTOR: RES 10K 1/16W 1% 0402; Chkd/date: VASANTHA/201216; Crtd /date: GEETHA/290506; Custom_Duty: 15%; Customs_HS_Code: 85332119; Distributor_name: DIGIKEY; Distributor_part_number: 311-10.0KLRTR-ND; Footprint Path: Y:\MIS_DATABASE\Library\ALTIUM_TOOL\PCB_FOOTPRINTS\Altium_Footprint_Lib.PcbLib; Height: 0.40MM; Library Path: Y:\MIS_DATABASE\Library\ALTIUM_TOOL\SCHEMATICS_PARTS\MS_DISCRETE_Library.schlib; Mfr_name: YAGEO AMERICA; Mfr_part_number: RC0402FR-0710KL; Mistral Part No: 110015090015-R; Package: 0402; Part_type: RESISTORS\FIXED; Project: VOCERA; RoHS: RoHS; Temperature: -55°C+155°C; Tolerance: 1%; Voltage: NA; Wattage: 1/16W; Weight: 0.65mg; Datasheet: Y:\MIS_DATABASE\DATASHEETS\RESISTORS\RCXXXXL-SER_MAR18.PDF
U35-U37 = TPS62872-Q1_VQFN16: IC 2.7-6V INPUT 15A STACKABLE FAST TRANSIENT SYNCHRONOUS STEP-DOWN DC-DC CONVERTER VQFN16; Chkd/date: ALVY/280322; Crtd /date: ALVY/280322; Custom_Duty: 15%; Customs_HS_Code: 85423100; Distributor_name: NA; Distributor_part_number: NA; Footprint Path: Y:\MIS_DATABASE\Library\ALTIUM_TOOL\PCB_FOOTPRINTS\Altium_Footprint_Lib.PcbLib; Height: 1.05MM; Library Path: Y:\MIS_DATABASE\Library\ALTIUM_TOOL\SCHEMATICS_PARTS\MS_MISCPOWER_Library.schlib; Manufacturer: TEXAS INSTRUMENTS; Mfr_name: TEXAS INSTRUMENTS; Mistral Part No: 142022030022; Package: VQFN16; Part_type: ICS\POWER\DC-DC CONVERTER; Project: TI_J7AHP_EVM_BRD; Remarks: CREATED SAME AS  TPS62873QWRXSR-Q1; RoHS: NA; Temperature: -40°C+150°C; Tolerance: NA; Voltage: NA; Wattage: NA; Weight: NA; Datasheet: Y:\MIS_DATABASE\DATASHEETS\ICS\POWER\TPS6287X-Q1.PDF
U216 U217 = MOSFET_2N7002BK: TRANSISTOR MOSFET N-CHANNEL 50V 200mA SOT-416F; Chkd/date: ALVY/220222; Crtd /date: TAMILARASU/180222; Custom_Duty: 15%; Customs_HS_Code: 85423100; Distributor_name: DIGIKEY; Distributor_part_number: RE1J002YNTCLCT-ND; Footprint Path: Y:\MIS_DATABASE\Library\ALTIUM_TOOL\PCB_FOOTPRINTS\Altium_Footprint_Lib.PcbLib; Height: 0.85MM; Library Path: Y:\MIS_DATABASE\Library\ALTIUM_TOOL\SCHEMATICS_PARTS\MS_MOSFET_Library.schlib; Manufacturer: ROHM; Mfr_name: ROHM; Mistral Part No: 130022020037-R; Package: SOT-416F; Part_type: TRANSISTOR\MOSFET; Project: TI_J7AHP_EVM_BRD; RoHS: RoHS; Temperature: -55°C+150°C; Tolerance: NA; Voltage: NA; Wattage: NA; Weight: 2.4mg; Datasheet: Y:\MIS_DATABASE\DATASHEETS\DISCRETES\TRANSISTORS_FETS\RE1J002YN.PDF

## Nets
DGND: C178.2 C179.2 C180.2 C181.2 C182.2 C183.2 C253.2 C254.2 C260.2 C261.2 C267.2 C271.2 C273.2 C277.2 C278.2 C281.2 C286.2 C288.2 C293.2 C294.2 C298.2 C299.2 C427.2 C705.2 C891.2 C892.2 C917.1 C928.2 C929.2 C941.1 C963.2 C973.2 C977.2 C985.2 C994.2 C1001.2 C1015.2 C1025.2 C1035.2 C1039.2 C1050.2 C1059.2 C1060.2 C1071.2 C1072.2 C1268.2 D30.2(ANODE) FL10.2 FL10.4 FL11.2 FL11.4 FL12.2 FL12.4 FL13.2 FL13.4 FL14.2 FL14.4 FL15.2 FL15.4 FL16.2 FL16.4 FL17.2 FL17.4 FL18.2 FL18.4 FL19.2 FL19.4 FL20.2 FL20.4 FL21.2 FL21.4 FL40.2 FL40.4 FL41.2 FL41.4 FL47.2 FL47.4 FL48.2 FL48.4 R189.2 R190.2 R192.2 R193.2 R195.2 R197.2 R201.2 R203.2 R659.1 R1079.1 R1122.1 U35.6(GND) U35.8(GND) U35.17(EP) U36.6(GND) U36.8(GND) U36.12(SDA) U36.13(SCL) U36.15(VSEL) U36.17(EP) U37.6(GND) U37.8(GND) U37.12(SDA) U37.13(SCL) U37.15(VSEL) U37.17(EP) U68.5(REFGND1) U68.6(REFGND2) U68.21(FB_B2) U68.36(VBACKUP) U68.57(GND) U134.3(GND) U137.2(S) U216.2(S) U217.2(S) U234.3(GND) U278.3(GND) ; also on sheet 11 12 13 14 15 16 17 18 20 21 22 23 24 25 26 27 28 29 30 31 32 33 34 35 36 37 38 39 40 41 42 43 44 45 46 47 48 49 50 51 52 53 54 55 56 57 58 59 60 61 62 63 64 65 66 67 68 71 72 73 76 77 78 79 81 82 83 84
VCCA_3V3: C260.1 C261.1 C278.1 C928.1 C929.1 C963.1 C973.1 C985.1 C1001.1 C1015.1 C1025.1 C1035.1 C1039.1 C1050.1 FL40.1 FL40.3 FL41.1 FL41.3 LD10.2 R206.1 R627.2 R908.1 R982.1 R1063.2 TP30.1(TP) U30.1(S1) U30.2(S2) U30.3(S3) U68.4(VCCA) U68.8(PVIN_LDO4) U68.10(PVIN_LDO3) U68.12(PVIN_LDO12) U68.35(PVIN_B5) U68.45(PVIN_B3) U68.48(VIO_IN) U68.54(PVIN_B4) U234.5(VCC) ; also on sheet 23 54 71 72 75 81
VCCA_3V3_CPU_AVS: FL10.1 FL10.3 FL11.1 FL11.3 FL12.1 FL12.3 FL13.1 FL13.3 FL14.1 FL14.3 FL15.1 FL15.3 FL16.1 FL16.3 FL17.1 FL17.3 FL18.1 FL18.3 FL19.1 FL19.3 FL20.1 FL20.3 FL21.1 FL21.3 R188.1 R191.1 R194.1 R196.1 U35.5(VIN1) U35.9(VIN2) U35.11(MODE/SYNC) U36.5(VIN1) U36.9(VIN2) U37.5(VIN1) U37.9(VIN2) ; also on sheet 75
VCCA_3V3_DDR: C293.1 C294.1 C1059.1 C1060.1 FL47.1 FL47.3 FL48.1 FL48.3 U68.17(PVIN_B2) U68.26(PVIN_B1) ; also on sheet 75
VDD_CPU_AVS: C178.1 C179.1 C180.1 C181.1 C182.1 C183.1 L24.2 L25.2 L26.2 R205.2 R208.2 ; also on sheet 22 27 28 54 74
VDD_CPU_HCPS_GOSNS: C154.1 C156.1 C158.1 R186.1 R201.1 R203.1 U35.2(GOSNS) U36.2(GOSNS) U37.2(GOSNS)
VDD_CPU_HCPS_SW1: L24.1 U35.7(SW)
VDD_CPU_HCPS_SW2: L25.1 U36.7(SW)
VDD_CPU_HCPS_SW3: L26.1 U37.7(SW)
VDD_CPU_HCPS_VOSNS: R205.1 R208.1 U35.3(VOSNS) U36.3(VOSNS) U37.3(VOSNS)
VDD_DDR_1V1: C298.1 C299.1 C1071.1 C1072.1 L33.2 L34.2 R557.2 U68.22(FB_B1) ; also on sheet 14 15 26 28 74 75
VDD_GPIORET_IO_3V3: C427.1 R647.2 U134.5(VCC) ; also on sheet 26 54 74
VDD_IO_1V8: U68.50(FB_B4) ; also on sheet 26 72 74
VDD_IO_1V8_REG: C253.1 C892.1 L30.2 ; also on sheet 74 75
VDD_MCU_0V85: U68.37(FB_B5) ; also on sheet 26 27 28 54 72 74
VDD_MCU_0V85_REG: C273.1 C994.1 L32.2 ; also on sheet 74
VDD_MCUIO_1V8: R448.2 ; also on sheet 26 54 74
VDD_MCUIO_1V8_REG: C288.1 U68.13(VOUT_LDO1) ; also on sheet 74 75
VDD_MCUIO_3V3_REG: C286.1 U68.11(VOUT_LDO2) ; also on sheet 74 75
VDD_PMIC_BUCK_SW1: L34.1 U68.27(SW_B1A) U68.28(SW_B1B)
VDD_PMIC_BUCK_SW2: L33.1 U68.15(SW_B2A) U68.16(SW_B2B)
VDD_PMIC_BUCK_SW3: L31.1 U68.43(SW_B3A) U68.44(SW_B3B)
VDD_PMIC_BUCK_SW4: L30.1 U68.55(SW_B4A) U68.56(SW_B4B)
VDD_PMIC_BUCK_SW5: L32.1 U68.34(SW_B5A)
VDD_RAM_0V85: U68.49(FB_B3) ; also on sheet 27 74
VDD_RAM_0V85_REG: C254.1 C891.1 L31.2 ; also on sheet 74
VINT_PMIC_1V8: C267.1 TP308.1(TP) U68.2(VOUT_LDOVINT)
AMUXOUT_A: TP130.1(TP) U68.1(AMUXOUT)
CAN_WKUP: R658.2 ; also on sheet 50
EN_3V3_VIO: U68.19(GPIO9) ; also on sheet 54 65 72
EN_DDR_RET_1V1: R557.1 U68.24(GPIO6) ; also on sheet 14 72
EN_DRV_OUT: R433.2 TP150.1(TP) U68.29(EN_DRV)
EN_GPIO_RET_3V3: R1063.1 U68.23(GPIO5) ; also on sheet 72
H_MAIN_WK0n: R645.1 ; also on sheet 18
H_MCU_INTn: R448.1 TP158.1(TP) U68.14(nINT) ; also on sheet 16
H_MCU_PORz: R1062.1 TP220.1(TP) U68.25(nRSTOUT) ; also on sheet 36
H_MCU_WK1n: R646.1 ; also on sheet 18
H_SOC_PORz: R1033.1 TP123.1(TP) U68.53(GPIO11) ; also on sheet 36
H_WKUP_I2C0_SCL: U35.13(SCL) U68.31(SCL_I2C1/SCK_SPI) ; also on sheet 23 54 71
H_WKUP_I2C0_SDA: U35.12(SDA) U68.30(SDA_I2C1/SDI_SPI) ; also on sheet 23 54 71
HCPS_A_CPU_FSEL_PH1: R194.2 R195.1 U35.16(FSEL)
HCPS_A_CPU_FSEL_PH2: R188.2 R189.1 U36.16(FSEL)
HCPS_A_CPU_FSEL_PH3: R191.2 R192.1 U37.16(FSEL)
HCPS_A_CPU_PG: C705.1 R907.2 TP38.1(TP)
HCPS_A_CPU_VSEL: R196.2 R197.1 U35.15(VSEL)
HCPS_A_SYNC_OUT_PH1: U35.14(SYNC_OUT) U36.11(MODE/SYNC)
HCPS_A_SYNC_OUT_PH2: R190.1 U36.14(SYNC_OUT) U37.11(MODE/SYNC)
HCPS_A_SYNC_OUT_PH3: R193.1 U37.14(SYNC_OUT)
LEOA_OSC32KCAP: C977.1 U68.40(OSC32KCAP)
LEOA_OSC32KIN: C941.2 U68.38(OSC32KIN) Y10.2
LEOA_OSC32KOUT: C917.2 U68.39(OSC32KOUT) Y10.1
MAIN_PWRGRP_IRQn: R206.2 U35.4(EN) U36.4(EN) U37.4(EN) U216.3(D) U234.2(A) ; also on sheet 54 71 72
MAIN_PWRGRP_IRQn_BUF: R1089.1 U234.4(Y)
MCU_I2C0_SCL: U68.32(GPIO1) ; also on sheet 18 43
MCU_I2C0_SDA: U68.33(GPIO2) ; also on sheet 18 43
MCU_PORZ_OUT: R1123.1 ; also on sheet 18 37 55
MCU_PWRGRP_IRQn: TP127.1(TP) U68.42(GPIO10) ; also on sheet 54 72
MCU_SAFETY_ERRZ: R1081.1 ; also on sheet 18
MCU_WK1n: R645.2 R646.2 R647.1 U134.2(A)
PB_CAN_WAKEn: R1302.1 ; also on sheet 35 50
PMIC_ENABLE: TP153.1(TP) U68.20(nPWRON/ENABLE) ; also on sheet 23
PMIC_GPIO3: R1035.2 U68.46(GPIO3)
PMIC_GPIO4: R1026.2 U68.47(GPIO4)
PMIC_GPIO7: R1081.2 U68.18(GPIO7)
PMIC_GPIO8: R398.2 U68.41(GPIO8)
PMIC_POWER_EN1: R1061.2 ; also on sheet 18
PMIC_WDOG_DISABLE: R398.1 R1061.1 R1079.2 R1089.2 ; also on sheet 23
R_CAN_WKUP: R658.1 R659.2 U137.1(G)
SOC_PORZ_OUT: R1111.1 ; also on sheet 18 30 32 37 43 51 56 59 60 62
SOC_PWR_WKn: R627.1 R1026.1 U134.4(Y) U137.3(D) U278.4(Y)
SOC_SAFETY_ERRZ: R1035.1 ; also on sheet 18
VDA_DLL_0V8: U217.1(G) ; also on sheet 25 74
VDA_DLL_0V8_REG: C281.1 U68.9(VOUT_LDO3) ; also on sheet 74
VDA_MCU_1V8: R1033.2 R1062.2 ; also on sheet 21 25 36 74
VDA_MCU_1V8_REG: C277.1 U68.7(VOUT_LDO4) ; also on sheet 18 74
VRTC_PMIC_1V8: C271.1 TP310.1(TP) U68.3(VOUT_LDOVRTC)
VSYS_3V3: C1268.1 R80.1 R1301.2 U30.5(D) U278.5(VCC) ; also on sheet 22 23 35 36 40 47 49 62 63 65 66 67 68 73 75 76 77 78 79
VSYS_SENSE: D30.1(CATHODE) R78.2 U68.51(VSYS_SENSE)
N35592192: R154.1 U30.4(G)
N35592194: R78.1 R80.2
N35592423: R154.2 U68.52(OVPGDRV)
N35593340: LD10.1 R433.1
N35595852: C154.2 C155.2 C156.2 C158.2 U35.1(COMP) U36.1(COMP) U37.1(COMP)
N35595856: R907.1 R908.2 U35.10(PG) U36.10(PG) U37.10(PG)
N35596954: C155.1 R186.2
N36834242: R982.2 U216.1(G) U217.3(D)
N36841285: R1111.2 R1122.2 R1123.2 U234.1(OE)
N40063454: R1301.1 R1302.2 U278.2(A)

Not connected (* = marked no-connect by the designer): U134 1(NC)*; U278 1(NC)*

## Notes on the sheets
sheet 69
- "PCB Notes":
  For multi-phase Buck converter configs, route remote sense
  feedback as follows:
   1. Use pseudo differential pair traces on same layer & next
  to primarily power plane segment. Avoid routing near to any
  noisy/switching signals.
   2. Ensure only 2x Point of Load (PoL) vias connect sense
  trace to Pwr & Gnd planes near the middle of SOC's
  power ball group.
   3. Ensure only PoL vias connect sense traces to Pwr or Gnd
  planes. All other vias (at buck component) must have Pwr &
  Gnd planes isolated.
   4. Trace widths = 4-8mil & separation  distance = 8-50mil,
  try to keep traces near each other as best as possible.
- For single-phase Buck converter configs,
  route remote sense feedback as follows:
   1. Use single-ended traces on same layer & next to
  primarily power plane segment as best as possible.
  Avoid routing near to any noisy/switching signals.
   2. Ensure only 1x PoL via connects sense trace to
  Pwr plane near the middle of SOC's power ball group.
   3. Ensure only PoL vias connect sense traces to Pwr
  or Gnd planes. All other vias (at buck component)
  must have Pwr & Gnd planes isolated.
   4. Trace widths = 4-8mil.
- PMIC
- Route as Pseudo diff pair traces
  (See "PCB Notes")
- Note: Keepout needs to be provided
   for the VDD_DDR_1V1 and Gnd vias of
   feedback pins connecting to the PMIC.
- FB_Voltage at Load
- Line to Shape keepout needs to be given in layout
  for VDD_DDR_1V1 and DGND feedback traces
- FB_Gnd/Ref at Load
- R1061 to be mounted during
  emulator debug requiring SoC
  to enable PMIC power resource
  (i.e. VDD_CORE)
- PMIC-A uses default I2C ADDR:
  0x48, 0x49, 0x4A & 0x4B
- SoC,Open-Drain,
  Active Low
- SN74LVC1G07 is used to isolate power from
  PMIC to SoC when SoC is powered off
- Active High
  1.8V logic
sheet 70
- VDD_CPU_AVS High-Current Power Stage A (HCPS-A)
- Note: Via keepout areas need to be applied to positive & negative remote sense traces/nets
  (i.e. “VDD_xxx_HCPS_VOSNS/_GOSNS”) both at the buck & along diff trace routing path between buck”xOSNS” pins
  to ensure no unwanted power or Gnd connections are made before reaching the desired remote sense location
  where only 1x power & Gnd connection should be made
- Line to Shape keepout needs to be given in layout
  for VDD_CPU_AVS and DGND feedback traces
- Buck EN control aligned to VDA_DLL_0V8
  for power seqs.
  Buck EN is bi-directional pin that both enables
  and reports status, see DS for details.
- Route remote sense as "VDD_xxx_P / _N"
  as pseudo differential pair trace.
- (See "PCB Notes")
- FB1_VDD_CPU_AVS_P
- FB1_VDD_CPU_AVS_N
- FB2_VDD_CPU_AVS_P
- FB2_VDD_CPU_AVS_N
- VSEL=> 0.8V Boot & 0x40 I2C ADDR
- FSEL = 2.25MHz
- Note: A 2nd alternative remote sense
  location & diff trace pair have been
  shown to enable TI internal evaluation
  & testing only. End products should use
  remote sense attached under SoC in
  middle of BGA power ball field.
  Any improved performance due to
  2nd remote sense location will be
  captured in future EVM SCH once
  test results are verified.
- FB_VDD_CPU_AVS_P
- FSEL = 2.25MHz
- FB_VDD_CPU_AVS_N
- FB_VDD_CPU_AVS_P
- FB_VDD_CPU_AVS_N
- FSEL = 2.25MHz
